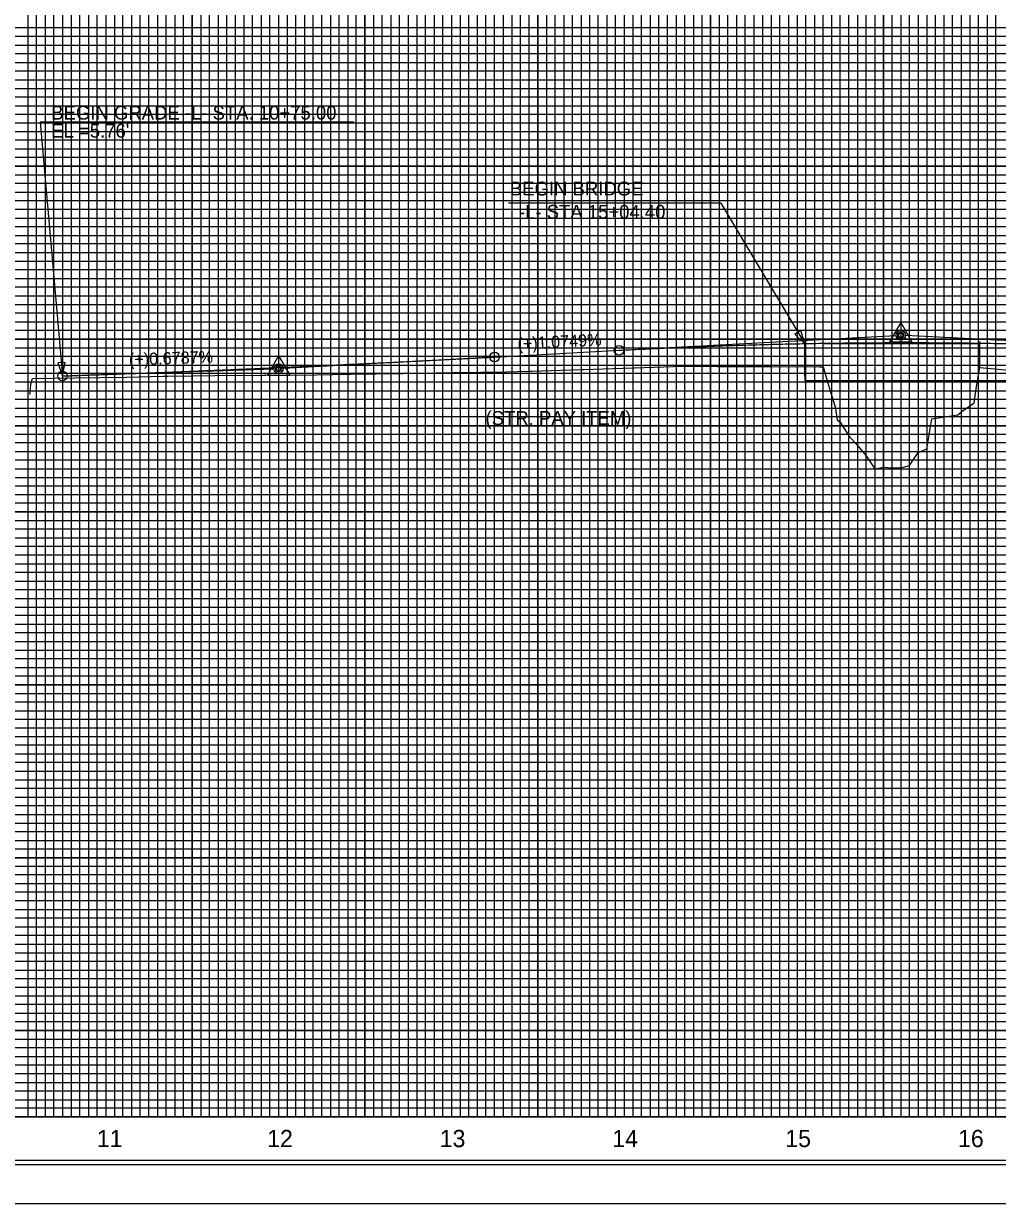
# Model space of a CAD drawing. Extents: x 575424 to 577182, y -52702 to -51602.
# Drawn here: x 575768 to 576331, y -52702 to -52020 of the extents above; entities that cross this region are included whole.
import ezdxf

# ---------------------------------------------------------------- set-up
doc = ezdxf.new("R2010")
doc.units = 0
for name, color, linetype in [('Exist Profile Cell', 7, 'Continuous'), ('Exist Vertical Profile Ground Line', 7, 'Continuous'), ('Exist Vertical Profile Horizontal Axis Label Major', 7, 'Continuous'), ('Prop PFL VPI Symbol CELL', 7, 'Continuous'), ('Prop Roadway Bridge', 7, 'Continuous'), ('Prop Vertical Profile Curve Label', 7, 'Continuous'), ('Prop Vertical Profile Ditch Grade Right Label', 7, 'Continuous'), ('Prop Vertical Profile Grade', 7, 'Continuous'), ('Prop Vertical Profile Grade Label', 7, 'Continuous'), ('Prop VPI Label', 7, 'Continuous'), ('Scratch_Level_1', 7, 'Continuous'), ('Scratch_Level_6', 7, 'Continuous'), ('Sheet Cutting Line CELL', 7, 'Continuous'), ('Sheet DOT Grid CELL', 7, 'Continuous'), ('Sheet Layout Profile Border', 7, 'Continuous'), ('Sheet Plot Border Inside CELL', 7, 'Continuous'), ('Sheet Plot Border Outside CELL', 7, 'Continuous'), ('Sheet Profile CELL', 7, 'Continuous'), ('Sheet Profile Grid Major CELL', 7, 'Continuous'), ('Sheet Profile Grid Middle CELL', 7, 'Continuous'), ('Sheet Profile Grid Minor CELL', 7, 'Continuous')]:
    doc.layers.add(name, color=color, linetype=linetype)

# ---------------------------------------------------------------- blocks, each defined once
blk = doc.blocks.new('Profile VPI Symbol')
at = {"layer": 'Prop PFL VPI Symbol CELL'}
for p, q in [((-0.001, 0.147), (-0.13, -0.077)), ((-0.001, 0.147), (0.129, -0.077)), ((-0.13, -0.077), (0.129, -0.077))]:
    blk.add_line(p, q, dxfattribs=at)
for radius in [0.035, 0.024]:
    blk.add_circle((-0.001, -0.003), radius, dxfattribs=at)

msp = doc.modelspace()

# ---------------------------------------------------------------- linework, layer by layer
at = {"layer": 'Exist Profile Cell'}
msp.add_line((575715.21, -52252.64), (576835.62, -52252.64), dxfattribs=at)
at = {"layer": 'Exist Vertical Profile Ground Line'}
msp.add_line((576237.34, -52241.75), (576238.49, -52249.16), dxfattribs=at)
for points in [[(575771.42, -52234.55), (575771.81, -52228.43), (575772.78, -52225.38), (575797.29, -52224.95), (575827.24, -52224.43), (575848.3, -52224.04), (575851.24, -52223.99), (575878.29, -52223.51), (575906.67, -52223.33), (575907.25, -52223.32), (575907.88, -52223.31), (575937.26, -52223.11), (575956.16, -52222.82), (575957.06, -52222.81), (575985.9, -52222.37), (575987.07, -52222.35), (576015.85, -52221.91), (576016.87, -52221.91), (576018.12, -52221.9), (576046.87, -52221.47), (576060.48, -52221.03), (576061.59, -52221), (576090.17, -52220.09), (576091.62, -52220.05), (576120.1, -52219.15), (576121.14, -52219.11), (576149.5, -52218.22), (576151.14, -52218.17), (576169.18, -52218.26), (576170.3, -52218.27), (576198.41, -52218.42), (576200.3, -52218.44), (576228.26, -52218.59), (576230.3, -52218.61), (576234.21, -52231.76), (576237.34, -52241.75)], [(576308.17, -52246.23), (576311.34, -52243.85), (576317.7, -52239.41), (576319.1, -52229.93), (576320.86, -52218.9), (576344.06, -52221.01)], [(576238.49, -52249.16), (576240.21, -52250.54), (576245.21, -52258.54), (576250.21, -52264.04), (576255.21, -52270.04), (576260.21, -52277.54), (576265.21, -52276.54), (576270.21, -52277.04), (576275.21, -52277.04), (576280.21, -52275.54), (576285.21, -52268.04), (576290.21, -52266.04), (576293.21, -52248.54), (576308.17, -52246.23)]]:
    msp.add_lwpolyline(points, dxfattribs=at)
at = {"layer": 'Prop Roadway Bridge'}
for p, q in [((576219.61, -52205.1), (576219.61, -52226.45)), ((576219.61, -52223.92), (576219.61, -52205.22)), ((576219.61, -52226.45), (576339.61, -52226.45))]:
    msp.add_line(p, q, dxfattribs=at)
at = {"layer": 'Prop Vertical Profile Grade'}
msp.add_line((576040.21, -52212.87), (576112.21, -52209), dxfattribs=at)
for points in [[(576112.21, -52209), (576118.73, -52208.66), (576125.25, -52208.33), (576131.77, -52208.01), (576138.29, -52207.71), (576144.81, -52207.42), (576151.33, -52207.15), (576157.85, -52206.88), (576164.37, -52206.64), (576170.89, -52206.4), (576177.41, -52206.18), (576183.93, -52205.98), (576190.45, -52205.79), (576196.97, -52205.61), (576203.49, -52205.44), (576210.01, -52205.29), (576216.53, -52205.16), (576223.05, -52205.03), (576229.57, -52204.92), (576236.09, -52204.83), (576242.61, -52204.74), (576249.13, -52204.68), (576255.65, -52204.62), (576262.17, -52204.58), (576268.69, -52204.55), (576275.21, -52204.54), (576281.73, -52204.54), (576288.25, -52204.55), (576294.77, -52204.58), (576301.29, -52204.62), (576307.81, -52204.68), (576314.33, -52204.75), (576320.85, -52204.83), (576327.37, -52204.93), (576333.89, -52205.04), (576340.41, -52205.16), (576346.93, -52205.3), (576353.45, -52205.45), (576359.97, -52205.62), (576366.49, -52205.8), (576373.01, -52205.99), (576379.53, -52206.2), (576386.05, -52206.42), (576392.57, -52206.65), (576399.09, -52206.9), (576405.61, -52207.16), (576412.13, -52207.44), (576418.65, -52207.73), (576425.17, -52208.03), (576431.69, -52208.35), (576438.21, -52208.68)], [(575790.21, -52223.83), (575795.21, -52223.66), (575800.21, -52223.49), (575805.21, -52223.31), (575810.21, -52223.14), (575815.21, -52222.96), (575820.21, -52222.78), (575825.21, -52222.59), (575830.21, -52222.41), (575835.21, -52222.22), (575840.21, -52222.03), (575845.21, -52221.84), (575850.21, -52221.65), (575855.21, -52221.46), (575860.21, -52221.26), (575865.21, -52221.06), (575870.21, -52220.86), (575875.21, -52220.66), (575880.21, -52220.46), (575885.21, -52220.25), (575890.21, -52220.04), (575895.21, -52219.83), (575900.21, -52219.62), (575905.21, -52219.4), (575910.21, -52219.19), (575915.21, -52218.97), (575920.21, -52218.75), (575925.21, -52218.53), (575930.21, -52218.3), (575935.21, -52218.08), (575940.21, -52217.85), (575945.21, -52217.62), (575950.21, -52217.39), (575955.21, -52217.15), (575960.21, -52216.92), (575965.21, -52216.68), (575970.21, -52216.44), (575975.21, -52216.2), (575980.21, -52215.95), (575985.21, -52215.71), (575990.21, -52215.46), (575995.21, -52215.21), (576000.21, -52214.96), (576005.21, -52214.7), (576010.21, -52214.45), (576015.21, -52214.19), (576020.21, -52213.93), (576025.21, -52213.67), (576030.21, -52213.4), (576035.21, -52213.14), (576040.21, -52212.87)]]:
    msp.add_spline(points, degree=3, dxfattribs=at)
at = {"layer": 'Prop Vertical Profile Grade Label'}
for p, q in [((575958.76, -52076.93), (575777.23, -52076.93)), ((576171.04, -52123.94), (576048.19, -52123.94))]:
    msp.add_line(p, q, dxfattribs=at)
for points in [[(575777.23, -52076.93), (575790.21, -52223.83)], [(576171.04, -52123.94), (576219.61, -52205.22)]]:
    msp.add_lwpolyline(points, dxfattribs=at)
for points in [[(576213.84, -52199.68), (576219.61, -52205.22), (576217.39, -52197.54)], [(575787.58, -52216.28), (575790.21, -52223.83), (575791.71, -52215.97)]]:
    msp.add_lwpolyline(points, close=True, dxfattribs=at)
at = {"layer": 'Prop VPI Label'}
for p, q in [((576112.21, -52209), (576272.46, -52200.39)), ((576438.21, -52208.68), (576277.96, -52200.38)), ((576040.21, -52212.87), (575917.96, -52219.44)), ((575790.21, -52223.83), (575912.46, -52219.68))]:
    msp.add_line(p, q, dxfattribs=at)
for centre in [(576275.21, -52200.34), (576040.21, -52212.87), (576112.21, -52209), (575915.21, -52219.59), (575790.21, -52223.83), (575790.21, -52223.83)]:
    msp.add_circle(centre, 2.75, dxfattribs=at)
at = {"layer": 'Scratch_Level_1'}
for p, q in [((576230.3, -52218.61), (576230.3, -52201.27)), ((576320.86, -52218.9), (576320.86, -52203.89)), ((576996.24, -52212.64), (575674.58, -52212.64))]:
    msp.add_line(p, q, dxfattribs=at)
at = {"layer": 'Scratch_Level_6'}
msp.add_line((576230.3, -52205.09), (576320.86, -52205.09), dxfattribs=at)
at = {"layer": 'Sheet Cutting Line CELL'}
msp.add_line((575498.21, -52702.49), (577182.21, -52702.49), dxfattribs=at)
at = {"layer": 'Sheet DOT Grid CELL'}
for p, q in [((575815.21, -51627.49), (575815.21, -52652.49)), ((575865.21, -51627.49), (575865.21, -52652.49)), ((575915.21, -51627.49), (575915.21, -52652.49)), ((575965.21, -51627.49), (575965.21, -52652.49)), ((576015.21, -51627.49), (576015.21, -52652.49)), ((576065.21, -51627.49), (576065.21, -52652.49)), ((576115.21, -51627.49), (576115.21, -52652.49)), ((576165.21, -51627.49), (576165.21, -52652.49)), ((576215.21, -51627.49), (576215.21, -52652.49)), ((576265.21, -51627.49), (576265.21, -52652.49)), ((576315.21, -51627.49), (576315.21, -52652.49)), ((575665.21, -52052.49), (577165.21, -52052.49)), ((575665.21, -52102.49), (577165.21, -52102.49)), ((575665.21, -52152.49), (577165.21, -52152.49)), ((575665.21, -52202.49), (577165.21, -52202.49)), ((575665.21, -52252.49), (577165.21, -52252.49)), ((575665.21, -52302.49), (577165.21, -52302.49)), ((575665.21, -52352.49), (577165.21, -52352.49)), ((575665.21, -52402.49), (577165.21, -52402.49)), ((575665.21, -52452.49), (577165.21, -52452.49)), ((575665.21, -52502.49), (577165.21, -52502.49)), ((575665.21, -52552.49), (577165.21, -52552.49)), ((575665.21, -52602.49), (577165.21, -52602.49))]:
    msp.add_line(p, q, dxfattribs=at)
at = {"layer": 'Sheet Layout Profile Border'}
msp.add_lwpolyline([(575715.21, -51627.49), (575715.21, -52652.49), (577115.21, -52652.49), (577115.21, -51765.04), (576965.16, -51765.04), (576965.16, -51627.49)], close=True, dxfattribs=at)
at = {"layer": 'Sheet Plot Border Inside CELL'}
msp.add_lwpolyline([(577177.71, -51624.94), (575511.21, -51624.94), (575511.21, -52680.04), (577177.71, -52680.04)], close=True, dxfattribs=at)
at = {"layer": 'Sheet Plot Border Outside CELL'}
msp.add_lwpolyline([(577182.21, -51602.49), (575498.21, -51602.49), (575498.21, -52702.49), (577182.21, -52702.49)], close=True, dxfattribs=at)
at = {"layer": 'Sheet Profile CELL'}
msp.add_line((577165.21, -52652.49), (575665.21, -52652.49), dxfattribs=at)
msp.add_lwpolyline([(577165.21, -51627.49), (575665.21, -51627.49), (575665.21, -52677.49), (577165.21, -52677.49)], close=True, dxfattribs=at)
at = {"layer": 'Sheet Profile Grid Major CELL'}
for points in [[(575815.21, -51627.49), (575815.21, -52652.49), (575865.21, -52652.49), (575865.21, -51627.49)], [(575915.21, -51627.49), (575915.21, -52652.49), (575965.21, -52652.49), (575965.21, -51627.49)], [(576015.21, -51627.49), (576015.21, -52652.49), (576065.21, -52652.49), (576065.21, -51627.49)], [(576115.21, -51627.49), (576115.21, -52652.49), (576165.21, -52652.49), (576165.21, -51627.49)], [(576215.21, -51627.49), (576215.21, -52652.49), (576265.21, -52652.49), (576265.21, -51627.49)], [(576315.21, -51627.49), (576315.21, -52652.49), (576365.21, -52652.49)], [(577165.21, -52102.49), (575665.21, -52102.49), (575665.21, -52052.49), (577165.21, -52052.49)], [(577165.21, -52202.49), (575665.21, -52202.49), (575665.21, -52152.49), (577165.21, -52152.49)], [(577165.21, -52302.49), (575665.21, -52302.49), (575665.21, -52252.49), (577165.21, -52252.49)], [(577165.21, -52402.49), (575665.21, -52402.49), (575665.21, -52352.49), (577165.21, -52352.49)], [(577165.21, -52502.49), (575665.21, -52502.49), (575665.21, -52452.49), (577165.21, -52452.49)], [(577165.21, -52602.49), (575665.21, -52602.49), (575665.21, -52552.49), (577165.21, -52552.49)]]:
    msp.add_lwpolyline(points, dxfattribs=at)
at = {"layer": 'Sheet Profile Grid Middle CELL'}
for points in [[(575790.21, -51627.49), (575790.21, -52652.49), (575840.21, -52652.49), (575840.21, -51627.49)], [(575890.21, -51627.49), (575890.21, -52652.49), (575940.21, -52652.49), (575940.21, -51627.49)], [(575990.21, -51627.49), (575990.21, -52652.49), (576040.21, -52652.49), (576040.21, -51627.49)], [(576090.21, -51627.49), (576090.21, -52652.49), (576140.21, -52652.49), (576140.21, -51627.49)], [(576190.21, -51627.49), (576190.21, -52652.49), (576240.21, -52652.49), (576240.21, -51627.49)], [(576290.21, -51627.49), (576290.21, -52652.49), (576340.21, -52652.49)], [(577165.21, -52027.49), (575665.21, -52027.49), (575665.21, -52077.49), (577165.21, -52077.49)], [(577165.21, -52127.49), (575665.21, -52127.49), (575665.21, -52177.49), (577165.21, -52177.49)], [(577165.21, -52227.49), (575665.21, -52227.49), (575665.21, -52277.49), (577165.21, -52277.49)], [(577165.21, -52327.49), (575665.21, -52327.49), (575665.21, -52377.49), (577165.21, -52377.49)], [(577165.21, -52427.49), (575665.21, -52427.49), (575665.21, -52477.49), (577165.21, -52477.49)], [(577165.21, -52527.49), (575665.21, -52527.49), (575665.21, -52577.49), (577165.21, -52577.49)], [(577165.21, -52627.49), (575665.21, -52627.49)]]:
    msp.add_lwpolyline(points, dxfattribs=at)
at = {"layer": 'Sheet Profile Grid Minor CELL'}
for points in [[(575770.21, -51627.49), (575770.21, -52652.49), (575775.21, -52652.49), (575775.21, -51627.49)], [(575780.21, -51627.49), (575780.21, -52652.49), (575785.21, -52652.49), (575785.21, -51627.49)], [(575795.21, -51627.49), (575795.21, -52652.49), (575800.21, -52652.49), (575800.21, -51627.49)], [(575805.21, -51627.49), (575805.21, -52652.49), (575810.21, -52652.49), (575810.21, -51627.49)], [(575820.21, -51627.49), (575820.21, -52652.49), (575825.21, -52652.49), (575825.21, -51627.49)], [(575830.21, -51627.49), (575830.21, -52652.49), (575835.21, -52652.49), (575835.21, -51627.49)], [(575845.21, -51627.49), (575845.21, -52652.49), (575850.21, -52652.49), (575850.21, -51627.49)], [(575855.21, -51627.49), (575855.21, -52652.49), (575860.21, -52652.49), (575860.21, -51627.49)], [(575870.21, -51627.49), (575870.21, -52652.49), (575875.21, -52652.49), (575875.21, -51627.49)], [(575880.21, -52652.49), (575885.21, -52652.49), (575885.21, -51627.49)], [(575880.21, -51627.49), (575880.21, -52652.49)], [(575895.21, -51627.49), (575895.21, -52652.49), (575900.21, -52652.49), (575900.21, -51627.49)], [(575905.21, -51627.49), (575905.21, -52652.49), (575910.21, -52652.49), (575910.21, -51627.49)], [(575920.21, -51627.49), (575920.21, -52652.49), (575925.21, -52652.49), (575925.21, -51627.49)], [(575930.21, -51627.49), (575930.21, -52652.49), (575935.21, -52652.49), (575935.21, -51627.49)], [(575945.21, -51627.49), (575945.21, -52652.49), (575950.21, -52652.49), (575950.21, -51627.49)], [(575955.21, -51627.49), (575955.21, -52652.49), (575960.21, -52652.49), (575960.21, -51627.49)], [(575970.21, -51627.49), (575970.21, -52652.49), (575975.21, -52652.49), (575975.21, -51627.49)], [(575980.21, -51627.49), (575980.21, -52652.49), (575985.21, -52652.49), (575985.21, -51627.49)], [(575995.21, -51627.49), (575995.21, -52652.49), (576000.21, -52652.49), (576000.21, -51627.49)], [(576005.21, -51627.49), (576005.21, -52652.49), (576010.21, -52652.49), (576010.21, -51627.49)], [(576020.21, -51627.49), (576020.21, -52652.49), (576025.21, -52652.49), (576025.21, -51627.49)], [(576030.21, -51627.49), (576030.21, -52652.49), (576035.21, -52652.49), (576035.21, -51627.49)], [(576045.21, -51627.49), (576045.21, -52652.49), (576060.21, -52652.49), (576060.21, -51627.49)], [(576050.21, -51627.49), (576050.21, -52652.49), (576055.21, -52652.49), (576055.21, -51627.49)], [(576050.21, -51628.09), (576050.21, -52652.49), (576055.21, -52652.49), (576055.21, -51628.09)], [(576070.21, -51627.49), (576070.21, -52652.49), (576075.21, -52652.49), (576075.21, -51627.49)], [(576080.21, -51627.49), (576080.21, -52652.49), (576085.21, -52652.49), (576085.21, -51627.49)], [(576095.21, -51627.49), (576095.21, -52652.49), (576100.21, -52652.49), (576100.21, -51627.49)], [(576105.21, -51627.49), (576105.21, -52652.49), (576110.21, -52652.49), (576110.21, -51627.49)], [(576120.21, -51627.49), (576120.21, -52652.49), (576125.21, -52652.49), (576125.21, -51627.49)], [(576130.21, -51627.49), (576130.21, -52652.49), (576135.21, -52652.49), (576135.21, -51627.49)], [(576145.21, -51627.49), (576145.21, -52652.49), (576150.21, -52652.49), (576150.21, -51627.49)], [(576155.21, -51627.49), (576155.21, -52652.49), (576160.21, -52652.49), (576160.21, -51627.49)], [(576170.21, -51627.49), (576170.21, -52652.49), (576175.21, -52652.49), (576175.21, -51627.49)], [(576180.21, -51627.49), (576180.21, -52652.49), (576185.21, -52652.49), (576185.21, -51627.49)], [(576195.21, -51627.49), (576195.21, -52652.49)], [(576200.21, -51627.49), (576200.21, -52652.49), (576205.21, -52652.49), (576205.21, -51627.49), (576210.21, -51627.49), (576210.21, -52652.49), (576220.21, -52652.49), (576220.21, -51627.49), (576225.21, -51627.49), (576225.21, -52652.49), (576230.21, -52652.49), (576230.21, -51627.49), (576235.21, -51627.49), (576235.21, -52652.49)], [(576245.21, -52652.49), (576245.21, -51627.49)], [(576250.21, -51627.49), (576250.21, -52652.49), (576255.21, -52652.49), (576255.21, -51627.49)], [(576260.21, -51627.49), (576260.21, -52652.49), (576270.21, -52652.49), (576270.21, -51627.49)], [(576275.21, -51627.49), (576275.21, -52652.49), (576275.21, -52652.49), (576280.21, -52652.49), (576280.21, -51627.49)], [(576285.21, -51627.49), (576285.21, -52652.49), (576295.21, -52652.49), (576295.21, -51627.49)], [(576300.21, -51627.49), (576300.21, -52652.49), (576305.21, -52652.49), (576305.21, -51627.49)], [(576310.21, -51627.49), (576310.21, -52652.49), (576320.21, -52652.49), (576320.21, -51627.49)], [(576325.21, -51627.49), (576325.21, -52652.49), (576330.21, -52652.49), (576330.21, -51627.49)], [(577115.21, -52022.49), (575715.21, -52022.49), (575715.21, -52032.49), (577115.21, -52032.49)], [(577115.21, -52037.49), (575715.21, -52037.49), (575715.21, -52042.49), (577115.21, -52042.49)], [(577115.21, -52047.49), (575715.21, -52047.49), (575715.21, -52057.49), (577115.21, -52057.49)], [(577115.21, -52062.49), (575715.21, -52062.49), (575715.21, -52067.49), (577115.21, -52067.49)], [(577115.21, -52072.49), (575715.21, -52072.49), (575715.21, -52082.49), (577115.21, -52082.49)], [(577115.21, -52087.49), (575715.21, -52087.49), (575715.21, -52092.49), (577115.21, -52092.49)], [(577115.21, -52097.49), (575715.21, -52097.49), (575715.21, -52107.49), (577115.21, -52107.49)], [(577115.21, -52112.49), (575715.21, -52112.49), (575715.21, -52117.49), (577115.21, -52117.49)], [(577115.21, -52122.49), (575715.21, -52122.49), (575715.21, -52132.49), (577115.21, -52132.49)], [(577115.21, -52137.49), (575715.21, -52137.49), (575715.21, -52142.49), (577115.21, -52142.49)], [(577115.21, -52147.49), (575715.21, -52147.49)], [(575715.21, -52157.49), (577115.21, -52157.49)], [(577115.21, -52162.49), (575715.21, -52162.49), (575715.21, -52167.49), (577115.21, -52167.49)], [(577115.21, -52172.49), (575715.21, -52172.49), (575715.21, -52182.49), (577115.21, -52182.49)], [(577115.21, -52187.49), (575715.21, -52187.49), (575715.21, -52192.49), (577115.21, -52192.49)], [(577115.21, -52197.49), (575715.21, -52197.49), (575715.21, -52207.49), (577115.21, -52207.49)], [(577115.21, -52212.49), (575715.21, -52212.49), (575715.21, -52217.49), (577115.21, -52217.49)], [(577115.21, -52222.49), (575715.21, -52222.49), (575715.21, -52232.49), (577115.21, -52232.49)], [(577115.21, -52237.49), (575715.21, -52237.49), (575715.21, -52242.49), (577115.21, -52242.49)], [(577115.21, -52247.49), (575715.21, -52247.49), (575715.21, -52257.49), (577115.21, -52257.49)], [(577115.21, -52262.49), (575715.21, -52262.49), (575715.21, -52267.49), (577115.21, -52267.49)], [(577115.21, -52272.49), (575715.21, -52272.49), (575715.21, -52282.49), (577115.21, -52282.49)], [(577115.21, -52287.49), (575715.21, -52287.49), (575715.21, -52292.49), (577115.21, -52292.49)], [(577115.21, -52297.49), (575715.21, -52297.49), (575715.21, -52307.49), (577115.21, -52307.49)], [(577115.21, -52312.49), (575715.21, -52312.49), (575715.21, -52317.49), (577115.21, -52317.49)], [(577115.21, -52322.49), (575715.21, -52322.49), (575715.21, -52332.49), (577115.21, -52332.49)], [(577115.21, -52337.49), (575715.21, -52337.49), (575715.21, -52342.49), (577115.21, -52342.49)], [(577115.21, -52347.49), (575715.21, -52347.49), (575715.21, -52357.49), (577115.21, -52357.49)], [(577115.21, -52362.49), (575715.21, -52362.49), (575715.21, -52367.49), (577115.21, -52367.49)], [(577115.21, -52372.49), (575715.21, -52372.49), (575715.21, -52382.49), (577115.21, -52382.49)], [(577115.21, -52387.49), (575715.21, -52387.49), (575715.21, -52392.49), (577115.21, -52392.49)], [(577115.21, -52397.49), (575715.21, -52397.49), (575715.21, -52407.49), (577115.21, -52407.49)], [(577115.21, -52412.49), (575715.21, -52412.49), (575715.21, -52417.49), (577115.21, -52417.49)], [(577115.21, -52422.49), (575715.21, -52422.49), (575715.21, -52432.49), (577115.21, -52432.49)], [(577115.21, -52437.49), (575715.21, -52437.49), (575715.21, -52442.49), (577115.21, -52442.49)], [(577115.21, -52447.49), (575715.21, -52447.49)], [(575715.21, -52457.49), (577115.21, -52457.49)], [(577115.21, -52462.49), (575715.21, -52462.49), (575715.21, -52467.49), (577115.21, -52467.49)], [(577115.21, -52472.49), (575715.21, -52472.49)], [(575715.21, -52482.49), (577115.21, -52482.49)], [(577115.21, -52487.49), (575715.21, -52487.49), (575715.21, -52492.49), (577115.21, -52492.49)], [(577115.21, -52497.49), (575715.21, -52497.49), (575715.21, -52507.49), (577115.21, -52507.49)], [(577115.21, -52512.49), (575715.21, -52512.49), (575715.21, -52517.49), (577115.21, -52517.49)], [(577115.21, -52522.49), (575715.21, -52522.49), (575715.21, -52532.49), (577115.21, -52532.49)], [(577115.21, -52537.49), (575715.21, -52537.49), (575715.21, -52542.49), (577115.21, -52542.49)], [(577115.21, -52547.49), (575715.21, -52547.49), (575715.21, -52557.49), (577115.21, -52557.49)], [(577115.21, -52562.49), (575715.21, -52562.49), (575715.21, -52567.49), (577115.21, -52567.49)], [(577115.21, -52572.49), (575715.21, -52572.49), (575715.21, -52582.49), (577115.21, -52582.49)], [(577115.21, -52587.49), (575715.21, -52587.49), (575715.21, -52592.49), (577115.21, -52592.49)], [(577115.21, -52597.49), (575715.21, -52597.49), (575715.21, -52607.49), (577115.21, -52607.49)], [(577115.21, -52612.49), (575715.21, -52612.49), (575715.21, -52617.49), (577115.21, -52617.49)], [(577115.21, -52622.49), (575715.21, -52622.49), (575715.21, -52632.49), (577115.21, -52632.49)], [(577115.21, -52637.49), (575715.21, -52637.49), (575715.21, -52642.49), (577115.21, -52642.49)], [(577115.21, -52647.49), (575715.21, -52647.49)]]:
    msp.add_lwpolyline(points, dxfattribs=at)

# ---------------------------------------------------------------- block references
at = {"layer": 'Prop Vertical Profile Ditch Grade Right Label', "xscale": 50, "yscale": 50}
for p in [(576275.25, -52200.21), (575915.25, -52219.46)]:
    msp.add_blockref('Profile VPI Symbol', p, dxfattribs=at)

# ---------------------------------------------------------------- texts
at = {"layer": 'Exist Vertical Profile Horizontal Axis Label Major'}
for s, p in [('11', (575810.08, -52669.95)), ('12', (575908.62, -52669.95)), ('13', (576008.46, -52669.95)), ('14', (576108.3, -52669.95)), ('15', (576208.39, -52669.95)), ('16', (576308.33, -52669.95))]:
    msp.add_text(s, height=10, dxfattribs=at).set_placement(p)
at = {"layer": 'Prop Vertical Profile Curve Label'}
for s, p in [('BEGIN GRADE -L- STA. 10+75.00', (575783.73, -52075.53)), ("EL =5.76'", (575783.7, -52085.94)), ('BEGIN BRIDGE ', (576049.06, -52119.43)), ('-L- STA 15+04.40', (576054.3, -52132.87)), ('(STR. PAY ITEM)', (576034.98, -52252.19))]:
    msp.add_text(s, height=8, dxfattribs=at).set_placement(p)
at = {"layer": 'Prop Vertical Profile Grade Label'}
for s, rotation, p in [('(+)1.0749%', 3.07642, (576053.63, -52208.76)), ('(+)0.6787%', 1.94349, (575828.78, -52217.81))]:
    msp.add_text(s, height=7, rotation=rotation, dxfattribs=at).set_placement(p)

doc.saveas('drawing.dxf')
